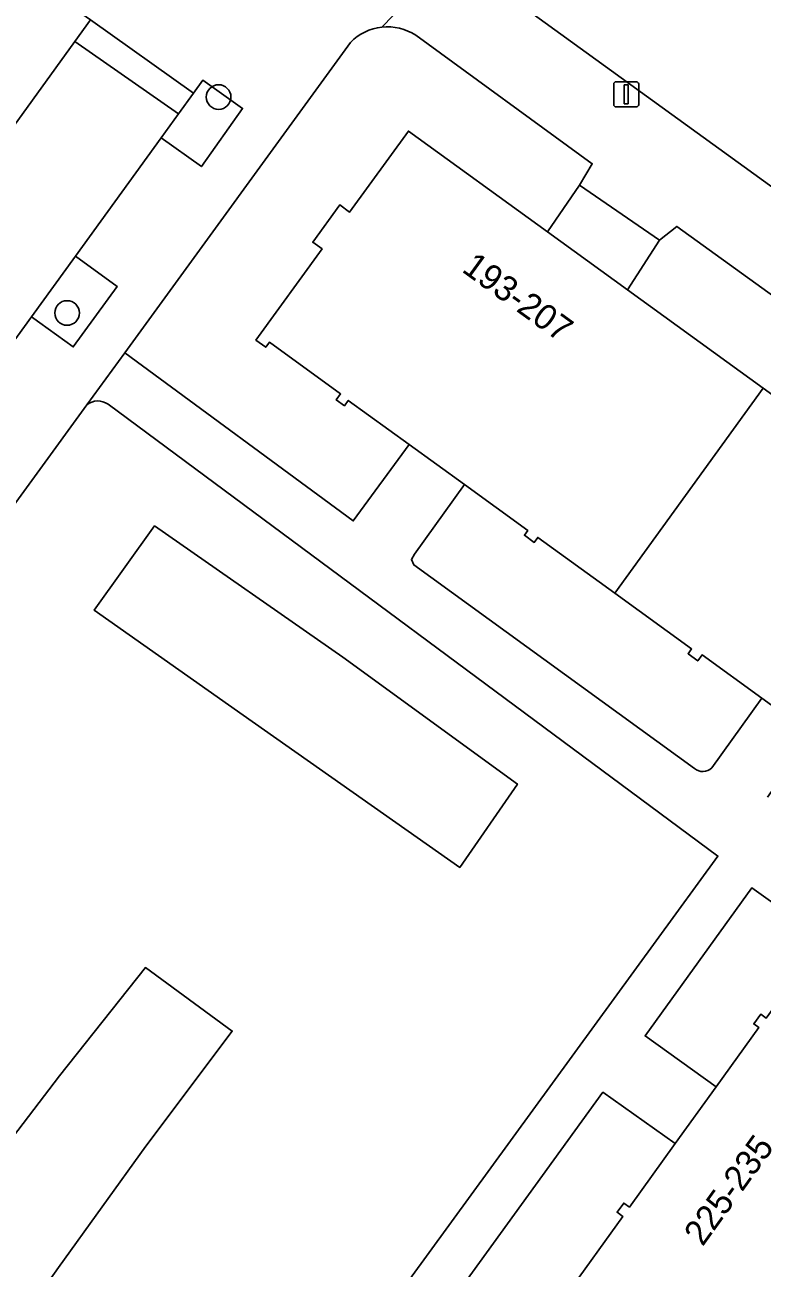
# Model space of a CAD drawing. Extents: x 160102 to 160934, y 382045 to 382923.
# Drawn here: x 160263.15 to 160292.45, y 382326.59 to 382375.99 of the extents above; entities that cross this region are included whole.
import ezdxf

# ---------------------------------------------------------------- set-up
doc = ezdxf.new("R2010")
doc.units = 0
for name, color, linetype in [('IMGEO_Berm_groen', 7, 'Continuous'), ('IMGEO_Boom', 7, 'Continuous'), ('IMGEO_Groenvoorziening', 7, 'Continuous'), ('IMGEO_Lichtmast', 7, 'Continuous'), ('IMGEO_Muur', 7, 'Continuous'), ('IMGEO_Pand', 7, 'Continuous'), ('IMGEO_Pand_nummerreeks', 7, 'Continuous'), ('IMGEO_Rijbaan_lokaal_open', 7, 'Continuous'), ('IMGEO_Voetpad_op_trap', 7, 'Continuous'), ('IMGEO_Voetpad_open', 7, 'Continuous')]:
    doc.layers.add(name, color=color, linetype=linetype)

msp = doc.modelspace()

# ---------------------------------------------------------------- linework, layer by layer
at = {"layer": 'IMGEO_Berm_groen'}
for points in [[(160265.141, 382375.329), (160265.762, 382376.188), (160263.74, 382377.608)], [(160257.638, 382364.962), (160265.141, 382375.329)]]:
    msp.add_lwpolyline(points, dxfattribs=at)
at = {"layer": 'IMGEO_Boom'}
for centre in [(160270.852, 382373.122), (160264.833, 382364.542)]:
    msp.add_circle(centre, 0.489, dxfattribs=at)
at = {"layer": 'IMGEO_Groenvoorziening'}
for points in [[(160276.095, 382375.293), (160267.128, 382362.963), (160276.204, 382356.28), (160278.421, 382359.315), (160276.005, 382361.066), (160275.851, 382360.854), (160275.526, 382361.089), (160275.699, 382361.328), (160272.871, 382363.377), (160272.727, 382363.178), (160272.334, 382363.463), (160274.96, 382367.086), (160274.593, 382367.351), (160275.667, 382368.833), (160276.056, 382368.551), (160278.391, 382371.772), (160283.925, 382367.761), (160285.195, 382369.616), (160285.7, 382370.469), (160278.683, 382375.576)], [(160265.62, 382360.89), (160225.112, 382305.189)], [(160290.693, 382342.966), (160266.46, 382360.915)], [(160290.063, 382350.958), (160289.891, 382350.72), (160289.503, 382351.002), (160289.645, 382351.198), (160286.59, 382353.412), (160283.535, 382355.626), (160283.39, 382355.428), (160283, 382355.711), (160283.136, 382355.898), (160280.616, 382357.724), (160278.631, 382354.961), (160278.515, 382354.752), (160278.603, 382354.53), (160289.764, 382346.45)], [(160290.443, 382346.473), (160292.432, 382349.241), (160290.063, 382350.958)], [(160225.411, 382304.277), (160249.799, 382286.841), (160290.693, 382342.966)]]:
    msp.add_lwpolyline(points, dxfattribs=at)
for points in [[(160270.17, 382370.359), (160271.806, 382372.668), (160270.225, 382373.788), (160269.851, 382373.272), (160269.254, 382372.449), (160268.564, 382371.497)], [(160289.052, 382367.984), (160288.365, 382367.43), (160287.103, 382365.457), (160292.49, 382361.552), (160297.865, 382357.657), (160299.205, 382359.518), (160299.671, 382360.321)], [(160263.418, 382364.395), (160265.076, 382363.193), (160266.819, 382365.598), (160265.16, 382366.799)], [(160265.911, 382352.73), (160268.307, 382356.084), (160275.787, 382350.861), (160282.727, 382345.827), (160280.432, 382342.513), (160271.831, 382348.557)], [(160268.307, 382356.084), (160265.911, 382352.73), (160271.831, 382348.557), (160280.432, 382342.513), (160282.727, 382345.827), (160275.787, 382350.861)], [(160292.117, 382336.297), (160292.391, 382336.676), (160292.603, 382336.522), (160294.643, 382339.348), (160294.454, 382339.485), (160294.689, 382339.81), (160292.04, 382341.704), (160287.794, 382335.818), (160290.624, 382333.799), (160292.321, 382336.149)], [(160267.941, 382338.532), (160271.392, 382336.008), (160267.963, 382331.433), (160264.484, 382326.611), (160259.863, 382320.106), (160256.394, 382315.297), (160254.082, 382312.033), (160250.595, 382307.169), (160246.818, 382309.96), (160251.423, 382316.262), (160255.24, 382321.442), (160258.878, 382326.533), (160262.276, 382331.284), (160264.525, 382334.233)], [(160271.392, 382336.008), (160267.941, 382338.532), (160264.525, 382334.233), (160262.276, 382331.284), (160258.878, 382326.533), (160255.24, 382321.442), (160251.423, 382316.262), (160246.818, 382309.96), (160250.595, 382307.169), (160254.082, 382312.033), (160256.394, 382315.297), (160259.863, 382320.106), (160264.484, 382326.611), (160267.963, 382331.433)], [(160284.707, 382325.577), (160286.918, 382328.639), (160286.683, 382328.809), (160286.95, 382329.179), (160287.173, 382329.018), (160288.992, 382331.538), (160286.118, 382333.581), (160277.712, 382321.965), (160280.574, 382319.922), (160282.192, 382322.164), (160282.002, 382322.302), (160282.273, 382322.677), (160282.497, 382322.515)]]:
    msp.add_lwpolyline(points, close=True, dxfattribs=at)
for centre, radius, start, end in [((160277.561, 382373.868), 2.045, 96.2565, 135.7992), ((160277.559, 382373.865), 2.047, 56.7052, 96.2066), ((160266.056, 382360.369), 0.679, 53.492, 129.9174), ((160290.092, 382346.815), 0.491, 228.1349, 315.7452)]:
    msp.add_arc(centre, radius, start, end, dxfattribs=at)
at = {"layer": 'IMGEO_Lichtmast'}
for p, q in [((160286.652, 382373.73), (160287.442, 382373.73)), ((160287.442, 382373.73), (160286.652, 382373.73)), ((160286.552, 382372.83), (160286.552, 382373.63)), ((160286.552, 382373.63), (160286.552, 382372.83)), ((160287.542, 382373.63), (160287.542, 382372.83)), ((160287.542, 382372.83), (160287.542, 382373.63)), ((160287.442, 382372.73), (160286.652, 382372.73)), ((160286.652, 382372.73), (160287.442, 382372.73))]:
    msp.add_line(p, q, dxfattribs=at)
msp.add_lwpolyline([(160286.972, 382373.605), (160287.122, 382373.605), (160287.122, 382372.855), (160286.972, 382372.855), (160286.972, 382373.605)], dxfattribs=at)
for centre, start, end in [((160286.652, 382373.63), 90, 180), ((160286.652, 382373.63), 90, 180), ((160287.442, 382373.63), 0, 90), ((160287.442, 382373.63), 360, 90), ((160286.652, 382372.83), 180, 270), ((160286.652, 382372.83), 180, 270), ((160287.442, 382372.83), 270, 0), ((160287.442, 382372.83), 270, 0)]:
    msp.add_arc(centre, 0.1, start, end, dxfattribs=at)
at = {"layer": 'IMGEO_Muur'}
for points in [[(160285.195, 382369.616), (160283.925, 382367.761)], [(160288.365, 382367.43), (160287.103, 382365.457)]]:
    msp.add_lwpolyline(points, dxfattribs=at)
at = {"layer": 'IMGEO_Pand'}
for points in [[(160292.49, 382361.552), (160287.103, 382365.457), (160283.925, 382367.761), (160278.391, 382371.772), (160276.056, 382368.551), (160275.667, 382368.833), (160274.593, 382367.351), (160274.96, 382367.086), (160272.334, 382363.463), (160272.727, 382363.178), (160272.871, 382363.377), (160275.699, 382361.328), (160275.526, 382361.089), (160275.851, 382360.854), (160276.005, 382361.066), (160278.421, 382359.315), (160280.616, 382357.724), (160283.136, 382355.898), (160283, 382355.711), (160283.39, 382355.428), (160283.535, 382355.626), (160286.59, 382353.412)], [(160306.558, 382351.356), (160301.079, 382355.327), (160297.865, 382357.657), (160292.49, 382361.552), (160286.59, 382353.412), (160289.645, 382351.198), (160289.503, 382351.002), (160289.891, 382350.72), (160290.063, 382350.958), (160292.432, 382349.241), (160294.427, 382347.795), (160297.178, 382345.801), (160297.002, 382345.559), (160300.536, 382342.998), (160303.185, 382346.653), (160303.546, 382346.391), (160304.613, 382347.864), (160304.229, 382348.142)], [(160302.989, 382333.815), (160298.77, 382336.861), (160299.027, 382337.217), (160297.557, 382338.279), (160297.301, 382337.925), (160294.689, 382339.81), (160294.454, 382339.485), (160294.643, 382339.348), (160292.603, 382336.522), (160292.391, 382336.676), (160292.117, 382336.297), (160292.321, 382336.149), (160290.624, 382333.799), (160288.992, 382331.538), (160287.173, 382329.018), (160286.95, 382329.179), (160286.683, 382328.809), (160286.918, 382328.639), (160284.707, 382325.577), (160292.818, 382319.723), (160296.785, 382325.219), (160298.996, 382328.283)]]:
    msp.add_lwpolyline(points, close=True, dxfattribs=at)
at = {"layer": 'IMGEO_Rijbaan_lokaal_open'}
for points in [[(160268.066, 382382.743), (160268.988, 382382.432), (160279.52, 382378.878), (160280.36, 382378.595), (160281.433, 382377.842), (160282.198, 382377.265), (160289.487, 382371.973), (160310.176, 382356.994), (160316.701, 382352.253)], [(160211.682, 382292.936), (160219.49, 382303.761), (160221.25, 382306.189), (160226.384, 382313.267), (160228.135, 382315.681), (160233.432, 382323.015), (160235.19, 382325.452), (160238.914, 382330.614), (160240.647, 382333.016), (160244.878, 382338.87), (160246.644, 382341.3), (160251.374, 382347.808), (160253.159, 382350.263), (160256.891, 382355.398), (160258.64, 382357.805), (160263.418, 382364.395), (160265.16, 382366.799), (160268.564, 382371.497), (160269.254, 382372.449), (160265.141, 382375.329), (160257.638, 382364.962), (160210.95, 382300.202), (160193.147, 382275.71), (160177.488, 382254.16)]]:
    msp.add_lwpolyline(points, dxfattribs=at)
msp.add_lwpolyline([(160265.762, 382376.188), (160265.141, 382375.329), (160269.254, 382372.449), (160269.851, 382373.272)], close=True, dxfattribs=at)
at = {"layer": 'IMGEO_Voetpad_op_trap'}
msp.add_lwpolyline([(160285.195, 382369.616), (160283.925, 382367.761), (160287.103, 382365.457), (160288.365, 382367.43)], close=True, dxfattribs=at)
at = {"layer": 'IMGEO_Voetpad_open'}
for points in [[(160310.176, 382356.994), (160289.487, 382371.973), (160282.198, 382377.265), (160281.433, 382377.842), (160280.36, 382378.595), (160279.52, 382378.878), (160279.141, 382377.768), (160277.338, 382375.9)], [(160277.338, 382375.9), (160279.141, 382377.768)], [(160263.74, 382377.608), (160265.762, 382376.188), (160269.851, 382373.272), (160270.225, 382373.788), (160271.806, 382372.668), (160270.17, 382370.359), (160268.564, 382371.497), (160265.16, 382366.799), (160266.819, 382365.598), (160265.076, 382363.193), (160263.418, 382364.395), (160258.64, 382357.805)], [(160211.365, 382289.074), (160214.663, 382290.822), (160223.192, 382302.55), (160225.112, 382305.189), (160265.62, 382360.89), (160267.128, 382362.963), (160276.095, 382375.293)], [(160278.683, 382375.576), (160285.7, 382370.469), (160285.195, 382369.616), (160288.365, 382367.43), (160289.052, 382367.984), (160299.671, 382360.321), (160299.205, 382359.518), (160302.357, 382357.283), (160302.994, 382357.936), (160315.871, 382348.622)], [(160289.764, 382346.45), (160278.603, 382354.53), (160278.515, 382354.752), (160278.631, 382354.961), (160280.616, 382357.724), (160278.421, 382359.315), (160276.204, 382356.28), (160267.128, 382362.963), (160265.62, 382360.89)], [(160266.46, 382360.915), (160290.693, 382342.966), (160249.799, 382286.841), (160225.411, 382304.277)], [(160292.66, 382345.304), (160294.427, 382347.795), (160292.432, 382349.241), (160290.443, 382346.473)], [(160257.334, 382293.871), (160265.95, 382305.772), (160268.754, 382303.631), (160270.257, 382305.713), (160267.379, 382307.808), (160276.065, 382319.688), (160278.92, 382317.632), (160280.574, 382319.922), (160277.712, 382321.965), (160286.118, 382333.581), (160288.992, 382331.538), (160290.624, 382333.799), (160287.794, 382335.818), (160292.04, 382341.704), (160294.689, 382339.81), (160297.301, 382337.925), (160297.557, 382338.279), (160299.027, 382337.217), (160298.77, 382336.861), (160302.989, 382333.815), (160305.087, 382332.308)]]:
    msp.add_lwpolyline(points, dxfattribs=at)
for centre, radius, start, end in [((160277.561, 382373.868), 2.045, 96.2565, 135.7992), ((160277.559, 382373.865), 2.047, 56.7052, 96.2066), ((160266.056, 382360.369), 0.679, 53.492, 129.9174), ((160290.092, 382346.815), 0.491, 228.1349, 315.7452)]:
    msp.add_arc(centre, radius, start, end, dxfattribs=at)

# ---------------------------------------------------------------- texts
at = {"layer": 'IMGEO_Pand_nummerreeks'}
for s, rotation, p in [('193-207', 324.0647, (160280.473, 382366.212)), ('225-235', 54.1903, (160290.083, 382327.422))]:
    msp.add_text(s, height=1, rotation=rotation, dxfattribs=at).set_placement(p)

doc.saveas('drawing.dxf')
